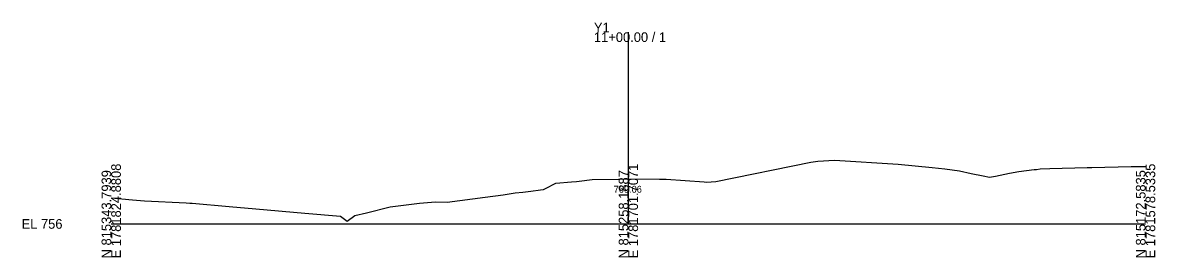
# Model space of a CAD drawing. Extents: x -26 to 3603, y -10 to 9847.
# Drawn here: x -25.7 to 302.8, y 990.3 to 1058.4 of the extents above; entities that cross this region are included whole.
import ezdxf

# ---------------------------------------------------------------- set-up
doc = ezdxf.new("R2010")
doc.units = 0
for name, color, linetype in [('Exist Cross Section Cell', 7, 'Continuous'), ('Exist XS Center Line Elevation Label', 7, 'Continuous'), ('Exist XS Ground Line', 7, 'Continuous')]:
    doc.layers.add(name, color=color, linetype=linetype)

msp = doc.modelspace()

# ---------------------------------------------------------------- linework, layer by layer
at = {"layer": 'Exist Cross Section Cell'}
for p, q in [((150, 1000), (150, 1055.58)), ((0, 1000), (150, 1000)), ((150, 1000), (300, 1000))]:
    msp.add_line(p, q, dxfattribs=at)
at = {"layer": 'Exist XS Ground Line'}
for p, q in [((204.95, 1018.2), (209.82, 1018.53)), ((209.82, 1018.53), (228.23, 1017.35)), ((175.4, 1012.34), (202.94, 1017.89)), ((202.94, 1017.89), (204.95, 1018.2)), ((228.23, 1017.35), (238.14, 1016.4)), ((238.14, 1016.4), (241.79, 1015.97)), ((241.79, 1015.97), (246.01, 1015.37)), ((246.01, 1015.37), (249.43, 1014.6)), ((260.51, 1014.68), (263.25, 1015.21)), ((263.25, 1015.21), (267.67, 1015.74)), ((267.67, 1015.74), (268.41, 1015.79)), ((268.41, 1015.79), (269.45, 1015.94)), ((269.45, 1015.94), (272.23, 1016.03)), ((272.23, 1016.03), (283.03, 1016.38)), ((283.03, 1016.38), (284.4, 1016.41)), ((284.4, 1016.41), (295.85, 1016.64)), ((295.85, 1016.64), (296.92, 1016.67)), ((296.92, 1016.67), (297.72, 1016.68)), ((297.72, 1016.68), (300, 1016.62)), ((128.93, 1011.8), (133.5, 1012.19)), ((133.5, 1012.19), (134.93, 1012.35)), ((134.93, 1012.35), (135.76, 1012.42)), ((135.76, 1012.42), (139.54, 1012.9)), ((139.54, 1012.9), (147.13, 1013.01)), ((147.13, 1013.01), (150.02, 1013.06)), ((150.02, 1013.06), (159, 1012.97)), ((159, 1012.97), (160.98, 1012.94)), ((160.98, 1012.94), (172.01, 1012.19)), ((172.01, 1012.19), (172.62, 1012.12)), ((172.62, 1012.12), (175.4, 1012.34)), ((249.43, 1014.6), (252.86, 1013.97)), ((252.86, 1013.97), (254.72, 1013.52)), ((254.72, 1013.52), (256.44, 1013.87)), ((256.44, 1013.87), (260.51, 1014.68)), ((113.72, 1008.48), (117.15, 1009.03)), ((117.15, 1009.03), (119.38, 1009.23)), ((119.38, 1009.23), (121.72, 1009.55)), ((121.72, 1009.55), (124.51, 1009.91)), ((124.51, 1009.91), (125.35, 1009.98)), ((125.35, 1009.98), (125.94, 1010.29)), ((125.94, 1010.29), (128.93, 1011.8)), ((0, 1007.54), (6.12, 1007.01)), ((6.12, 1007.01), (9.66, 1006.66)), ((9.66, 1006.66), (21.77, 1006.1)), ((21.77, 1006.1), (22.76, 1006.03)), ((22.76, 1006.03), (23.43, 1006)), ((23.43, 1006), (34.23, 1005.03)), ((80.95, 1004.97), (89.37, 1006.05)), ((89.37, 1006.05), (94.09, 1006.44)), ((94.09, 1006.44), (97.42, 1006.36)), ((97.42, 1006.36), (108.42, 1007.79)), ((108.42, 1007.79), (113.72, 1008.48)), ((34.23, 1005.03), (41.93, 1004.34)), ((41.93, 1004.34), (56.16, 1003.14)), ((56.16, 1003.14), (66.51, 1002.26)), ((66.51, 1002.26), (68.44, 1000.79)), ((68.44, 1000.79), (70.67, 1002.45)), ((70.67, 1002.45), (73.99, 1003.17)), ((73.99, 1003.17), (80.95, 1004.97))]:
    msp.add_line(p, q, dxfattribs=at)

# ---------------------------------------------------------------- texts
at = {"layer": 'Exist Cross Section Cell'}
for s, p in [('Y1', (140, 1055.58)), ('11+00.00 / 1', (140, 1052.78)), ('EL 756', (-26, 998.6))]:
    msp.add_text(s, height=2.8, dxfattribs=at).set_placement(p)
for s, p in [('N 815343.7939', (0, 990)), ('E 1781824.8808', (2.8, 990)), ('N 815258.1887', (150, 990)), ('E 1781701.7071', (152.8, 990)), ('N 815172.5835', (300, 990)), ('E 1781578.5335', (302.8, 990))]:
    msp.add_text(s, height=2.8, rotation=90, dxfattribs=at).set_placement(p)
at = {"layer": 'Exist XS Center Line Elevation Label'}
msp.add_text('769.06', height=2, dxfattribs=at).set_placement((145.73, 1009.06))

doc.saveas('drawing.dxf')
